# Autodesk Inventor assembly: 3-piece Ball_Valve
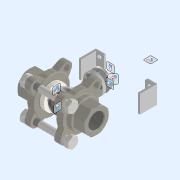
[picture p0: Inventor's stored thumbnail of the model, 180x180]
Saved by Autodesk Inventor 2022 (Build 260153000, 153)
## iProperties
Created: 2015-07
Part Number: 3-piece Ball_Valve
Description: STEP AP214
Document SubType Name: Assembly
Designer: admin
Sending System: PARTsolutions
Title: G:/3-piece Ball_Valve.stp
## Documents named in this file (31)
- C:\Users\admin\Desktop\valve\3-piece Ball_Valve.iam
- C:\Users\admin\Desktop\valve\_DN10  Packing.ipt
- C:\Users\admin\Desktop\valve\_DN10  Packing_1.ipt
- C:\Users\admin\Desktop\valve\_DN10  Packing_2.ipt
- C:\Users\admin\Desktop\valve\_DN10  Packing_7.ipt
- C:\Users\admin\Desktop\valve\_DN10  Packing_8.ipt
- C:\Users\admin\Desktop\valve\_DN10  Packing_9.ipt
- C:\Users\admin\Desktop\valve\_DN10  Packing_10.ipt
- C:\Users\admin\Desktop\valve\_DN10  Packing_11.ipt
- C:\Users\admin\Desktop\valve\_DN10  Packing_12.ipt
- C:\Users\admin\Desktop\valve\_DN10  Packing_13.ipt
- C:\Users\admin\Desktop\valve\_DN10  Packing_14.ipt
- C:\Users\admin\Desktop\valve\_DN10  Packing_15.ipt
- C:\Users\admin\Desktop\valve\_DN10  Packing_16.ipt
- C:\Users\admin\Desktop\valve\_DN10  Packing_17.ipt
- C:\Users\admin\Desktop\valve\_DN10  Packing_18.ipt
- C:\Users\admin\Desktop\valve\_DN10  Packing_19.ipt
- C:\Users\admin\Desktop\valve\_DN10  Packing_20.ipt
- C:\Users\admin\Desktop\valve\_DN10  Packing_21.ipt
- C:\Users\admin\Desktop\valve\_DN10  Packing_22.ipt
- C:\Users\admin\Desktop\valve\_DN10  Packing_23.ipt
- C:\Users\admin\Desktop\valve\_DN10  Packing_24.ipt
- C:\Users\admin\Desktop\valve\_DN10  Packing_25.ipt
- C:\Users\admin\Desktop\valve\Servo_20kg.ipt
- C:\Users\admin\Desktop\valve\disco.mg995.Al.ipt
- C:\Users\admin\Desktop\valve\blocco_perno_sfera.ipt
- C:\Users\admin\Desktop\valve\blocco_perno.ipt
- C:\Users\admin\Documents\Inventor\Content Center Files\R2022\it-IT\AS 1112 (4)\AS 1112 - M6(2).ipt
- C:\Users\admin\Documents\Inventor\Content Center Files\R2022\it-IT\AS 1110\AS 1110 - M2 x 12.ipt
- C:\Users\admin\Documents\Inventor\Content Center Files\R2022\it-IT\AS 1112 (2)\AS 1112 - M2,5  Tipo 5.ipt
- C:\Users\admin\Desktop\valve\blocco_servo.ipt
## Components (36 placed, 30 different names)
1. _DN10  Packing — Coincidente:14, Coincidente:15, Coincidente:17, Coincidente:21
2. _DN10  Packing_1 — Coincidente:15, Coincidente:16, Coincidente:21
3. _DN10  Packing_2 — Coincidente:14, Coincidente:17, Coincidente:18
4. _DN10  Packing_7 — Coincidente:16, Coincidente:18, Coincidente:19, Coincidente:20, Angolo:1, Coincidente:22, Allineato:3, Coincidente:23, Coincidente:24, Coincidente:25, Angolo:3, Angolo:4, Coincidente:27, Angolo:5
5. _DN10  Packing_8 — Coincidente:2, Allineato:2, Coincidente:3, Coincidente:19, Coincidente:20, Angolo:1
6. _DN10  Packing_9 — Rotazionale:1
7. _DN10  Packing_10 — Coincidente:1, Allineato:1
8. _DN10  Packing_11 — Rotazionale:10
9. _DN10  Packing_12 — Rotazionale:11
10. _DN10  Packing_13 — Rotazionale:13
11. _DN10  Packing_14 — Rotazionale:12
12. _DN10  Packing_15 — Rotazionale:7, Rotazionale:11
13. _DN10  Packing_16 — Rotazionale:6, Rotazionale:10
14. _DN10  Packing_17 — Rotazionale:9, Rotazionale:13
15. _DN10  Packing_18 — Rotazionale:8, Rotazionale:12
16. _DN10  Packing_19 — Coincidente:6, Coincidente:7, Coincidente:9, Rotazionale:6, Rotazionale:7, Rotazionale:8, Rotazionale:9
17. _DN10  Packing_20 — Coincidente:11, Rotazionale:2
18. _DN10  Packing_21 — Coincidente:13, Rotazionale:5
19. _DN10  Packing_22 — Coincidente:12, Rotazionale:4
20. _DN10  Packing_23 — Coincidente:10, Rotazionale:3
21. _DN10  Packing_24 — Coincidente:4, Coincidente:5, Coincidente:8, Coincidente:10, Coincidente:11, Coincidente:12, Coincidente:13, Rotazionale:2, Rotazionale:3, Rotazionale:4, Rotazionale:5
22. _DN10  Packing_25 — Coincidente:1, Allineato:1, Coincidente:2, Allineato:2, Coincidente:3, Rotazionale:1, Coincidente:4, Coincidente:5, Coincidente:6, Coincidente:7, Coincidente:8, Coincidente:9, Angolo:2, Angolo:3
23. Servo_20kg:1 — Coincidente:22, Angolo:2, Rotazionale:14, Allineato:4
24. disco.mg995.Al:1 — Rotazionale:14, Coincidente:25, Angolo:4, Coincidente:26
25. blocco_perno_sfera:1 — Allineato:3, Coincidente:26
26. blocco_perno:1 — Coincidente:23, Coincidente:24, Coincidente:27, Coincidente:29
27. AS 1112 (4) - Metrico M6:1 — Angolo:5
28. AS 1110 - Metrico M2 x 12:1
29. AS 1110 - Metrico M2 x 12:2
30. AS 1110 - Metrico M2 x 12:3
31. AS 1110 - Metrico M2 x 12:4
32. AS 1112 (2) - Metrico M2,5  Tipo 5:5 — Coincidente:29
33. AS 1112 (2) - Metrico M2,5  Tipo 5:1
34. AS 1112 (2) - Metrico M2,5  Tipo 5:2
35. AS 1112 (2) - Metrico M2,5  Tipo 5:4
36. blocco_servo:1 — Allineato:4
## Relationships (51: Mate 28, RevoluteJoint 14, Angle 5, Flush 4)
- Coincidente:1 [Mate]: _DN10  Packing_10 ↔ _DN10  Packing_25
- Allineato:1 [Flush]: _DN10  Packing_10 ↔ _DN10  Packing_25
- Coincidente:2 [Mate]: _DN10  Packing_8 ↔ _DN10  Packing_25
- Allineato:2 [Flush]: _DN10  Packing_8 ↔ _DN10  Packing_25
- Coincidente:3 [Mate]: _DN10  Packing_8 ↔ _DN10  Packing_25
- Rotazionale:1 [RevoluteJoint]: _DN10  Packing_9 ↔ _DN10  Packing_25
- Coincidente:4 [Mate]: _DN10  Packing_24 ↔ _DN10  Packing_25
- Coincidente:5 [Mate]: _DN10  Packing_24 ↔ _DN10  Packing_25
- Coincidente:6 [Mate]: _DN10  Packing_19 ↔ _DN10  Packing_25
- Coincidente:7 [Mate]: _DN10  Packing_19 ↔ _DN10  Packing_25
- Coincidente:8 [Mate]: _DN10  Packing_24 ↔ _DN10  Packing_25
- Coincidente:9 [Mate]: _DN10  Packing_19 ↔ _DN10  Packing_25
- Coincidente:10 [Mate]: _DN10  Packing_23 ↔ _DN10  Packing_24
- Coincidente:11 [Mate]: _DN10  Packing_20 ↔ _DN10  Packing_24
- Coincidente:12 [Mate]: _DN10  Packing_22 ↔ _DN10  Packing_24
- Coincidente:13 [Mate]: _DN10  Packing_21 ↔ _DN10  Packing_24
- Coincidente:14 [Mate]: _DN10  Packing ↔ _DN10  Packing_2
- Coincidente:15 [Mate]: _DN10  Packing ↔ _DN10  Packing_1
- Coincidente:16 [Mate]: _DN10  Packing_1 ↔ _DN10  Packing_7
- Coincidente:17 [Mate]: _DN10  Packing ↔ _DN10  Packing_2
- Coincidente:18 [Mate]: _DN10  Packing_2 ↔ _DN10  Packing_7
- Coincidente:19 [Mate]: _DN10  Packing_7 ↔ _DN10  Packing_8
- Coincidente:20 [Mate]: _DN10  Packing_7 ↔ _DN10  Packing_8
- Rotazionale:2 [RevoluteJoint]: _DN10  Packing_20 ↔ _DN10  Packing_24
- Rotazionale:3 [RevoluteJoint]: _DN10  Packing_23 ↔ _DN10  Packing_24
- Rotazionale:4 [RevoluteJoint]: _DN10  Packing_22 ↔ _DN10  Packing_24
- Rotazionale:5 [RevoluteJoint]: _DN10  Packing_21 ↔ _DN10  Packing_24
- Rotazionale:6 [RevoluteJoint]: _DN10  Packing_16 ↔ _DN10  Packing_19
- Rotazionale:7 [RevoluteJoint]: _DN10  Packing_15 ↔ _DN10  Packing_19
- Rotazionale:8 [RevoluteJoint]: _DN10  Packing_18 ↔ _DN10  Packing_19
- Rotazionale:9 [RevoluteJoint]: _DN10  Packing_17 ↔ _DN10  Packing_19
- Rotazionale:10 [RevoluteJoint]: _DN10  Packing_11 ↔ _DN10  Packing_16
- Rotazionale:11 [RevoluteJoint]: _DN10  Packing_12 ↔ _DN10  Packing_15
- Rotazionale:12 [RevoluteJoint]: _DN10  Packing_14 ↔ _DN10  Packing_18
- Rotazionale:13 [RevoluteJoint]: _DN10  Packing_13 ↔ _DN10  Packing_17
- Coincidente:21 [Mate]: _DN10  Packing ↔ _DN10  Packing_1
- Angolo:1 [Angle]: _DN10  Packing_7 ↔ _DN10  Packing_8
- Coincidente:22 [Mate]: _DN10  Packing_7 ↔ Servo_20kg:1
- Angolo:2 [Angle]: _DN10  Packing_25 ↔ Servo_20kg:1
- Rotazionale:14 [RevoluteJoint]: Servo_20kg:1 ↔ disco.mg995.Al:1
- Allineato:3 [Flush]: _DN10  Packing_7 ↔ blocco_perno_sfera:1
- Coincidente:23 [Mate]: _DN10  Packing_7 ↔ blocco_perno:1
- Coincidente:24 [Mate]: _DN10  Packing_7 ↔ blocco_perno:1
- Coincidente:25 [Mate]: _DN10  Packing_7 ↔ disco.mg995.Al:1
- Angolo:3 [Angle]: _DN10  Packing_7 ↔ _DN10  Packing_25
- Angolo:4 [Angle]: _DN10  Packing_7 ↔ disco.mg995.Al:1
- Coincidente:26 [Mate]: disco.mg995.Al:1 ↔ blocco_perno_sfera:1
- Coincidente:27 [Mate]: _DN10  Packing_7 ↔ blocco_perno:1
- Coincidente:29 [Mate]: blocco_perno:1 ↔ AS 1112 (2) - Metrico M2,5  Tipo 5:5
- Angolo:5 [Angle]: _DN10  Packing_7 ↔ AS 1112 (4) - Metrico M6:1
- Allineato:4 [Flush]: Servo_20kg:1 ↔ blocco_servo:1
